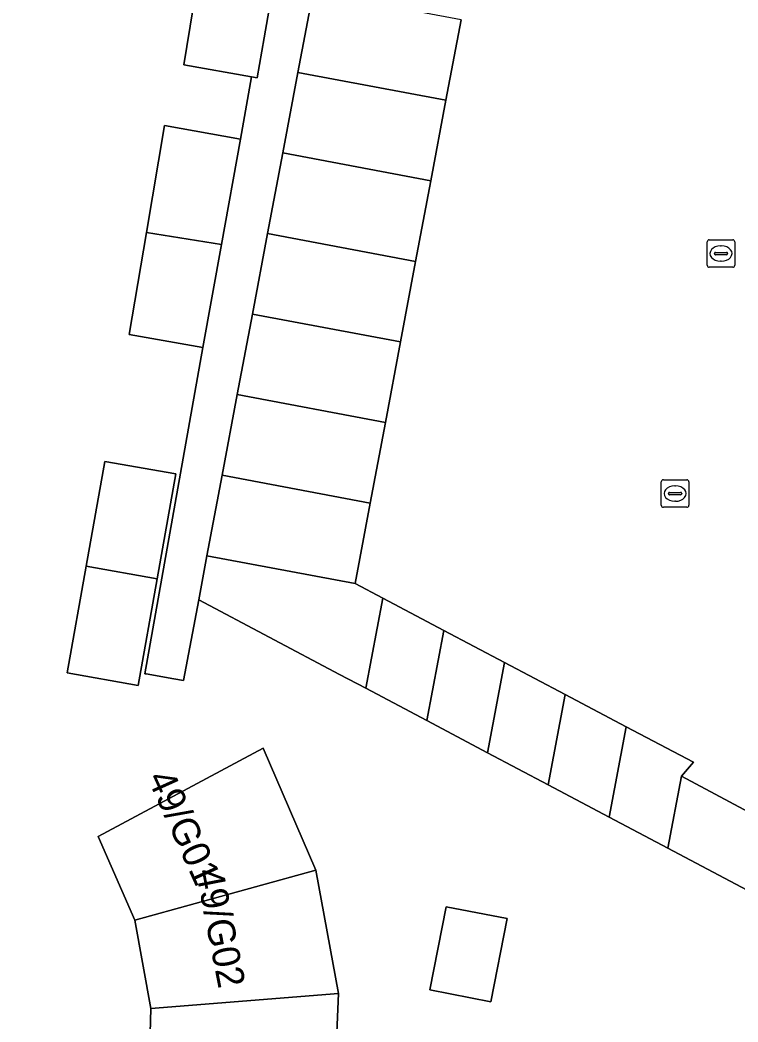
# Model space of a CAD drawing. Extents: x 161402 to 161933, y 381647 to 382315.
# Drawn here: x 161820.96 to 161847.06, y 381837.12 to 381873.54 of the extents above; entities that cross this region are included whole.
import ezdxf

# ---------------------------------------------------------------- set-up
doc = ezdxf.new("R2010")
doc.units = 0
for name, color, linetype in [('IMGEO_Erf', 7, 'Continuous'), ('IMGEO_Kolk', 7, 'Continuous'), ('IMGEO_Pand', 7, 'Continuous'), ('IMGEO_Pand_nummerreeks', 7, 'Continuous'), ('IMGEO_Parkeervlak_open', 7, 'Continuous'), ('IMGEO_Voetpad_open', 7, 'Continuous')]:
    doc.layers.add(name, color=color, linetype=linetype)

msp = doc.modelspace()

# ---------------------------------------------------------------- linework, layer by layer
at = {"layer": 'IMGEO_Erf'}
for points in [[(161827.603, 381861.635), (161824.926, 381862.113), (161825.552, 381865.821), (161826.209, 381869.714), (161828.968, 381869.215), (161829.372, 381871.479), (161826.915, 381871.917), (161827.949, 381878.216)], [(161852.346, 381833.514), (161853.347, 381839.11), (161852.213, 381839.723), (161848.95, 381841.485), (161848.885, 381841.123), (161848.012, 381841.585), (161844.517, 381843.436), (161842.378, 381844.568), (161840.167, 381845.738), (161837.957, 381846.908), (161835.747, 381848.078), (161833.537, 381849.248), (161832.579, 381849.755), (161827.453, 381852.469), (161826.9, 381849.53), (161826.551, 381849.592), (161825.549, 381849.77), (161825.489, 381849.781), (161827.603, 381861.635)]]:
    msp.add_lwpolyline(points, dxfattribs=at)
for points in [[(161823.358, 381853.686), (161824.035, 381857.49), (161826.623, 381857.044), (161825.944, 381853.225), (161825.253, 381849.351), (161822.667, 381849.811)], [(161825.632, 381834.487), (161825.716, 381837.606), (161825.13, 381840.815), (161823.801, 381843.856), (161829.804, 381847.078), (161831.717, 381842.638), (161832.532, 381838.148), (161832.326, 381833.3), (161831.022, 381828.853), (161828.579, 381824.737), (161825.227, 381821.282), (161820.956, 381826.404), (161823.067, 381828.511), (161824.629, 381831.199)], [(161836.451, 381841.309), (161838.666, 381840.875), (161838.073, 381837.848), (161835.858, 381838.282)]]:
    msp.add_lwpolyline(points, close=True, dxfattribs=at)
at = {"layer": 'IMGEO_Kolk'}
for p, q in [((161845.947, 381864.629), (161845.947, 381865.481)), ((161846.022, 381865.555), (161846.874, 381865.555)), ((161846.948, 381865.481), (161846.948, 381864.629)), ((161846.206, 381865.049), (161846.206, 381865.061)), ((161846.249, 381865.098), (161846.647, 381865.098)), ((161846.435, 381865.335), (161846.46, 381865.335)), ((161846.69, 381865.061), (161846.69, 381865.049)), ((161846.644, 381865.012), (161846.246, 381865.012)), ((161846.458, 381864.775), (161846.433, 381864.775)), ((161846.874, 381864.555), (161846.022, 381864.555)), ((161844.277, 381855.903), (161844.277, 381856.755)), ((161844.352, 381856.829), (161845.204, 381856.829)), ((161845.278, 381856.755), (161845.278, 381855.903)), ((161844.536, 381856.323), (161844.536, 381856.335)), ((161844.579, 381856.372), (161844.977, 381856.372)), ((161844.765, 381856.609), (161844.79, 381856.609)), ((161845.02, 381856.335), (161845.02, 381856.323)), ((161844.974, 381856.286), (161844.576, 381856.286)), ((161844.788, 381856.049), (161844.763, 381856.049)), ((161845.204, 381855.829), (161844.352, 381855.829))]:
    msp.add_line(p, q, dxfattribs=at)
for points in [[(161845.947, 381864.629), (161845.947, 381865.481)], [(161846.022, 381865.555), (161846.874, 381865.555)], [(161846.948, 381865.481), (161846.948, 381864.629)], [(161846.874, 381864.555), (161846.022, 381864.555)], [(161844.277, 381855.903), (161844.277, 381856.755)], [(161844.352, 381856.829), (161845.204, 381856.829)], [(161845.278, 381856.755), (161845.278, 381855.903)], [(161845.204, 381855.829), (161844.352, 381855.829)]]:
    msp.add_lwpolyline(points, dxfattribs=at)
for centre, radius, start, end in [((161846.024, 381865.479), 0.0765, 91.552, 178.448), ((161846.024, 381865.479), 0.0765, 91.552, 178.448), ((161846.872, 381865.479), 0.0765, 1.552, 88.448), ((161846.872, 381865.479), 0.0765, 1.552, 88.448), ((161846.246, 381865.058), 0.0403, 85.8775, 175.7526), ((161846.651, 381865.06), 0.0386, 1.7309, 96.639), ((161846.243, 381865.048), 0.0366, 178.938, 274.7102), ((161846.647, 381865.055), 0.043, 264.8664, 352.4533), ((161846.024, 381864.631), 0.0765, 181.552, 268.448), ((161846.024, 381864.631), 0.0765, 181.552, 268.448), ((161846.872, 381864.631), 0.0765, 271.552, 358.448), ((161846.872, 381864.631), 0.0765, 271.552, 358.448), ((161844.354, 381856.753), 0.0765, 91.552, 178.448), ((161844.354, 381856.753), 0.0765, 91.552, 178.448), ((161845.202, 381856.753), 0.0765, 1.552, 88.448), ((161845.202, 381856.753), 0.0765, 1.552, 88.448), ((161844.576, 381856.332), 0.0403, 85.8775, 175.7526), ((161844.573, 381856.322), 0.0366, 178.938, 274.7102), ((161844.977, 381856.329), 0.043, 264.8664, 352.4533), ((161844.981, 381856.334), 0.0386, 1.7309, 96.639), ((161844.354, 381855.905), 0.0765, 181.552, 268.448), ((161844.354, 381855.905), 0.0765, 181.552, 268.448), ((161845.202, 381855.905), 0.0765, 271.552, 358.448), ((161845.202, 381855.905), 0.0765, 271.552, 358.448)]:
    msp.add_arc(centre, radius, start, end, dxfattribs=at)
for centre, major_axis, ratio, start_param, end_param in [((161846.434, 381865.055), (-0.387, 0.002), 0.722429, 4.712389, 7.853982), ((161846.459, 381865.055), (-0.39, 0.002), 0.717154, 1.570796, 4.712389), ((161844.764, 381856.329), (-0.387, 0.002), 0.722429, 4.712389, 7.853982), ((161844.789, 381856.329), (-0.39, 0.002), 0.717154, 1.570796, 4.712389)]:
    msp.add_ellipse(centre, major_axis=major_axis, ratio=ratio, start_param=start_param, end_param=end_param, dxfattribs=at)
at = {"layer": 'IMGEO_Pand'}
for points in [[(161830.679, 381877.773), (161827.949, 381878.216), (161826.915, 381871.917), (161829.372, 381871.479), (161829.578, 381871.442), (161829.832, 381872.901)], [(161831.06, 381871.641), (161836.446, 381870.628), (161836.997, 381873.556), (161831.611, 381874.57)], [(161830.509, 381868.712), (161835.895, 381867.699), (161836.446, 381870.628), (161831.06, 381871.641)], [(161828.277, 381865.379), (161828.968, 381869.215), (161826.209, 381869.714), (161825.552, 381865.821)], [(161829.958, 381865.784), (161835.343, 381864.77), (161835.895, 381867.699), (161830.509, 381868.712)], [(161828.277, 381865.379), (161825.552, 381865.821), (161824.926, 381862.113), (161827.603, 381861.635)], [(161829.958, 381865.784), (161829.407, 381862.855), (161834.792, 381861.842), (161835.343, 381864.77)], [(161829.407, 381862.855), (161828.856, 381859.927), (161834.241, 381858.913), (161834.792, 381861.842)], [(161833.69, 381855.985), (161834.241, 381858.913), (161828.856, 381859.927), (161828.305, 381856.998)], [(161826.623, 381857.044), (161824.035, 381857.49), (161823.358, 381853.686), (161825.944, 381853.225)], [(161833.69, 381855.985), (161828.305, 381856.998), (161827.754, 381854.069), (161833.139, 381853.056)], [(161827.453, 381852.469), (161832.579, 381849.755), (161833.537, 381849.248), (161834.153, 381852.521), (161833.139, 381853.056), (161827.754, 381854.069)], [(161825.944, 381853.225), (161823.358, 381853.686), (161822.667, 381849.811), (161825.253, 381849.351)], [(161836.363, 381851.354), (161834.153, 381852.521), (161833.537, 381849.248), (161835.747, 381848.078)], [(161836.363, 381851.354), (161835.747, 381848.078), (161837.957, 381846.908), (161838.574, 381850.186)], [(161838.574, 381850.186), (161837.957, 381846.908), (161840.167, 381845.738), (161840.785, 381849.019)], [(161842.996, 381847.852), (161840.785, 381849.019), (161840.167, 381845.738), (161842.378, 381844.568)], [(161844.517, 381843.436), (161845.009, 381846.053), (161845.444, 381846.559), (161842.996, 381847.852), (161842.378, 381844.568)], [(161831.717, 381842.638), (161829.804, 381847.078), (161823.801, 381843.856), (161825.13, 381840.815)], [(161844.517, 381843.436), (161848.012, 381841.585), (161848.503, 381844.194), (161845.009, 381846.053)], [(161831.717, 381842.638), (161825.13, 381840.815), (161825.716, 381837.606), (161832.532, 381838.148)], [(161838.073, 381837.848), (161838.666, 381840.875), (161836.451, 381841.309), (161835.858, 381838.282)], [(161832.326, 381833.3), (161832.532, 381838.148), (161825.716, 381837.606), (161825.632, 381834.487)]]:
    msp.add_lwpolyline(points, close=True, dxfattribs=at)
at = {"layer": 'IMGEO_Parkeervlak_open'}
msp.add_lwpolyline([(161836.997, 381873.556), (161836.446, 381870.628), (161835.895, 381867.699), (161835.343, 381864.77), (161834.792, 381861.842), (161834.241, 381858.913), (161833.69, 381855.985), (161833.139, 381853.056), (161834.153, 381852.521), (161836.363, 381851.354), (161838.574, 381850.186), (161840.785, 381849.019), (161842.996, 381847.852), (161845.444, 381846.559), (161845.009, 381846.053), (161848.503, 381844.194), (161852.795, 381867.004), (161853.071, 381866.952), (161853.371, 381868.549), (161858.508, 381867.582), (161859.14, 381870.938), (161853.748, 381871.965), (161855.839, 381882.938)], dxfattribs=at)
at = {"layer": 'IMGEO_Voetpad_open'}
msp.add_lwpolyline([(161830.679, 381877.773), (161829.832, 381872.901), (161829.578, 381871.442), (161829.372, 381871.479), (161828.968, 381869.215), (161828.277, 381865.379), (161827.603, 381861.635), (161825.489, 381849.781), (161825.549, 381849.77), (161826.551, 381849.592), (161826.9, 381849.53), (161827.453, 381852.469), (161827.754, 381854.069), (161828.305, 381856.998), (161828.856, 381859.927), (161829.407, 381862.855), (161829.958, 381865.784), (161830.509, 381868.712), (161831.06, 381871.641), (161831.611, 381874.57)], dxfattribs=at)

# ---------------------------------------------------------------- texts
at = {"layer": 'IMGEO_Pand_nummerreeks'}
for s, rotation, p in [('49/G01', 294.2277, (161825.57, 381845.997)), ('49/G02', 281.0235, (161827.344, 381842.604))]:
    msp.add_text(s, height=1, rotation=rotation, dxfattribs=at).set_placement(p)

doc.saveas('drawing.dxf')
